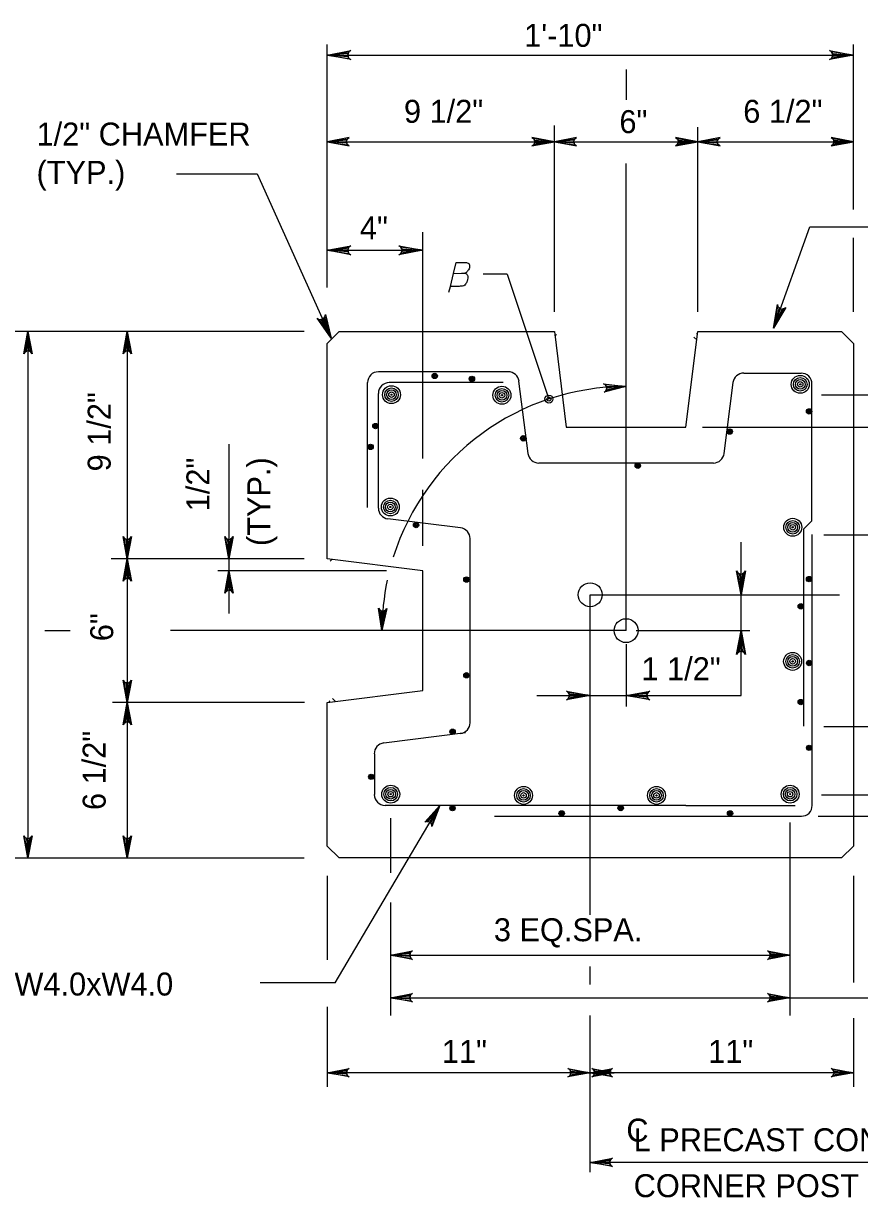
# Model space of a CAD drawing. Extents: x 3351 to 8430, y -3586 to 1457.
# Drawn here: x 5121.6 to 5233.4, y 162.9 to 319.9 of the extents above; entities that cross this region are included whole.
import ezdxf

# ---------------------------------------------------------------- set-up
doc = ezdxf.new("R2010")
doc.units = 0
doc.layers.add('1', color=7, linetype='Continuous')

msp = doc.modelspace()

# ---------------------------------------------------------------- linework, layer by layer
at = {"layer": '1'}
for p, q in [((5162.22, 284.6), (5162.22, 317.1)), ((5232.6, 295.01), (5232.6, 317.1)), ((5162.22, 315.67), (5232.6, 315.67)), ((5202.2, 313.73), (5202.2, 309.67)), ((5192.61, 281.36), (5192.61, 306.24)), ((5211.8, 281.36), (5211.8, 306.05)), ((5162.21, 304.09), (5192.61, 304.09)), ((5192.61, 304.09), (5211.8, 304.09)), ((5211.8, 304.09), (5232.6, 304.09)), ((5202.2, 238.72), (5202.2, 301.2)), ((5142.08, 299.79), (5152.85, 299.79)), ((5175.02, 261.75), (5175.02, 292)), ((5221.93, 279.14), (5226.77, 292.7)), ((5226.77, 292.7), (5234.76, 292.7)), ((5232.6, 281.36), (5232.6, 291.22)), ((5162.22, 289.57), (5175.02, 289.57)), ((5186.32, 286.38), (5183.09, 286.38)), ((5186.32, 286.38), (5191.88, 269.68)), ((5159.15, 278.72), (5120.24, 278.72)), ((5122.21, 278.72), (5122.21, 208.32)), ((5135.5, 278.72), (5135.5, 248.31)), ((5162.22, 277.12), (5163.82, 278.72)), ((5163.81, 278.72), (5192.61, 278.72)), ((5192.61, 278.72), (5194.21, 265.92)), ((5192.92, 278.33), (5192.68, 278.1)), ((5210.2, 265.92), (5211.8, 278.72)), ((5211.66, 277.58), (5211.26, 277.98)), ((5211.75, 278.3), (5211.6, 278.45)), ((5211.8, 278.72), (5231, 278.72)), ((5231, 278.72), (5232.6, 277.12)), ((5162.22, 248.31), (5162.22, 277.12)), ((5232.6, 277.12), (5232.6, 209.92)), ((5186.45, 273.33), (5169.08, 273.33)), ((5217.93, 273.15), (5225.6, 273.15)), ((5167.63, 255.18), (5167.63, 271.88)), ((5185.75, 271.88), (5170.53, 271.88)), ((5189.09, 262.4), (5187.88, 272.06)), ((5215.31, 262.4), (5216.5, 271.88)), ((5227.04, 253.41), (5227.04, 271.7)), ((5169.08, 255.11), (5169.08, 270.43)), ((5228.35, 270.27), (5236.82, 270.27)), ((5194.21, 265.92), (5210.2, 265.92)), ((5212.4, 265.92), (5245.08, 265.92)), ((5149.09, 263.63), (5149.09, 248.31)), ((5213.88, 261.13), (5190.52, 261.13)), ((5175.02, 250.07), (5175.02, 257.56)), ((5180.07, 252.46), (5170.35, 253.67)), ((5225.95, 252.31), (5227.04, 253.41)), ((5225.95, 225.96), (5225.95, 252.31)), ((5227.08, 215.36), (5227.08, 251.56)), ((5228.63, 251.51), (5244.51, 251.51)), ((5181.34, 226.41), (5181.34, 251.02)), ((5217.58, 230.05), (5217.58, 250.55)), ((5159.15, 248.31), (5133.35, 248.31)), ((5135.5, 248.31), (5135.5, 229.12)), ((5149.09, 248.31), (5149.09, 246.71)), ((5175.02, 246.71), (5162.22, 248.31)), ((5162.61, 248), (5162.84, 248.24)), ((5170.16, 246.71), (5147.6, 246.71)), ((5149.09, 246.71), (5149.09, 241.01)), ((5175.02, 230.72), (5175.02, 246.71)), ((5197.41, 243.52), (5230.75, 243.52)), ((5197.41, 200.73), (5197.41, 243.52)), ((5197.41, 243.52), (5197.41, 243.52)), ((5124.48, 238.72), (5127.87, 238.72)), ((5202.2, 238.72), (5141.28, 238.72)), ((5202.2, 238.72), (5202.2, 238.72)), ((5203.53, 238.72), (5218.77, 238.72)), ((5202.2, 236.92), (5202.2, 228.57)), ((5162.22, 229.12), (5175.02, 230.72)), ((5162.64, 229.17), (5162.49, 229.32)), ((5163.36, 229.26), (5162.96, 229.66)), ((5190.27, 230.05), (5217.58, 230.05)), ((5159.22, 229.12), (5133.54, 229.12)), ((5135.5, 229.12), (5135.5, 208.32)), ((5162.22, 209.92), (5162.22, 229.12)), ((5180.72, 225.05), (5169.8, 223.69)), ((5228.63, 225.92), (5244.81, 225.92)), ((5168.54, 222.26), (5168.54, 216.81)), ((5228.35, 216.77), (5241.27, 216.77)), ((5163.29, 191.65), (5177.28, 215.36)), ((5210.21, 215.36), (5169.98, 215.36)), ((5210.21, 215.36), (5224.83, 215.36)), ((5170.68, 213.66), (5170.68, 206.34)), ((5184.61, 213.91), (5225.64, 213.91)), ((5227.89, 213.91), (5245.08, 213.91)), ((5224.09, 213.06), (5224.09, 187.28)), ((5163.82, 208.32), (5162.22, 209.92)), ((5232.6, 209.92), (5231, 208.32)), ((5120.24, 208.32), (5159.15, 208.32)), ((5231, 208.32), (5163.82, 208.32)), ((5162.22, 205.94), (5162.22, 194.71)), ((5232.6, 205.94), (5232.6, 191.67)), ((5170.68, 202.36), (5170.68, 187.28)), ((5170.68, 195.33), (5224.09, 195.33)), ((5197.41, 191.4), (5197.41, 193.79)), ((5163.29, 191.65), (5153.25, 191.65)), ((5162.22, 188.43), (5162.22, 177.74)), ((5170.68, 189.64), (5224.09, 189.64)), ((5224.09, 189.64), (5237.91, 189.64)), ((5197.41, 166.32), (5197.41, 187.28)), ((5232.6, 186.91), (5232.6, 177.74)), ((5197.41, 179.6), (5162.21, 179.6)), ((5232.61, 179.6), (5197.41, 179.6)), ((5258.68, 167.61), (5197.41, 167.61))]:
    msp.add_line(p, q, dxfattribs=at)
for points in [[(5162.22, 315.67), (5165.4, 316.27), (5165.15, 316.1), (5165.03, 315.88), (5164.99, 315.67), (5165.03, 315.46), (5165.15, 315.24), (5165.4, 315.07), (5162.22, 315.67), (5165.15, 315.24), (5165.03, 315.46), (5162.22, 315.67), (5164.99, 315.67), (5165.03, 315.88), (5162.22, 315.67), (5165.15, 316.1)], [(5232.6, 315.67), (5229.42, 315.07), (5229.67, 315.24), (5229.79, 315.46), (5229.83, 315.67), (5229.79, 315.88), (5229.67, 316.1), (5229.42, 316.27), (5232.6, 315.67), (5229.67, 316.1), (5229.79, 315.88), (5232.6, 315.67), (5229.83, 315.67), (5229.79, 315.46), (5232.6, 315.67), (5229.67, 315.24)], [(5162.21, 304.09), (5165.19, 303.53), (5164.96, 303.69), (5164.84, 303.89), (5164.81, 304.09), (5164.84, 304.29), (5164.96, 304.49), (5165.19, 304.65), (5162.21, 304.09), (5164.96, 304.49), (5164.84, 304.29), (5162.21, 304.09), (5164.81, 304.09), (5164.84, 303.89), (5162.21, 304.09), (5164.96, 303.69)], [(5192.61, 304.09), (5189.62, 304.65), (5189.85, 304.49), (5189.97, 304.29), (5190.01, 304.09), (5189.97, 303.89), (5189.85, 303.69), (5189.62, 303.53), (5192.61, 304.09), (5189.85, 303.69), (5189.97, 303.89), (5192.61, 304.09), (5190.01, 304.09), (5189.97, 304.29), (5192.61, 304.09), (5189.85, 304.49)], [(5192.61, 304.09), (5195.59, 303.53), (5195.36, 303.69), (5195.24, 303.89), (5195.21, 304.09), (5195.24, 304.29), (5195.36, 304.49), (5195.59, 304.65), (5192.61, 304.09), (5195.36, 304.49), (5195.24, 304.29), (5192.61, 304.09), (5195.21, 304.09), (5195.24, 303.89), (5192.61, 304.09), (5195.36, 303.69)], [(5211.8, 304.09), (5208.82, 304.65), (5209.05, 304.49), (5209.17, 304.29), (5209.2, 304.09), (5209.17, 303.89), (5209.05, 303.69), (5208.82, 303.53), (5211.8, 304.09), (5209.05, 303.69), (5209.17, 303.89), (5211.8, 304.09), (5209.2, 304.09), (5209.17, 304.29), (5211.8, 304.09), (5209.05, 304.49)], [(5211.8, 304.09), (5214.79, 303.53), (5214.56, 303.69), (5214.44, 303.89), (5214.4, 304.09), (5214.44, 304.29), (5214.56, 304.49), (5214.79, 304.65), (5211.8, 304.09), (5214.56, 304.49), (5214.44, 304.29), (5211.8, 304.09), (5214.4, 304.09), (5214.44, 303.89), (5211.8, 304.09), (5214.56, 303.69)], [(5232.6, 304.09), (5229.62, 304.65), (5229.85, 304.49), (5229.97, 304.29), (5230, 304.09), (5229.97, 303.89), (5229.85, 303.69), (5229.62, 303.53), (5232.6, 304.09), (5229.85, 303.69), (5229.97, 303.89), (5232.6, 304.09), (5230, 304.09), (5229.97, 304.29), (5232.6, 304.09), (5229.85, 304.49)], [(5152.88, 299.79), (5162.75, 277.83)], [(5162.22, 289.57), (5165.4, 290.17), (5165.15, 290), (5165.03, 289.78), (5164.99, 289.57), (5165.03, 289.36), (5165.15, 289.14), (5165.4, 288.97), (5162.22, 289.57), (5165.15, 289.14), (5165.03, 289.36), (5162.22, 289.57), (5164.99, 289.57), (5165.03, 289.78), (5162.22, 289.57), (5165.15, 290)], [(5175.02, 289.57), (5171.83, 288.97), (5172.08, 289.14), (5172.21, 289.36), (5172.24, 289.57), (5172.21, 289.78), (5172.08, 290), (5171.83, 290.17), (5175.02, 289.57), (5172.08, 290), (5172.21, 289.78), (5175.02, 289.57), (5172.24, 289.57), (5172.21, 289.36), (5175.02, 289.57), (5172.08, 289.14)], [(5179.13, 286.48), (5179.48, 287.95), (5180.85, 287.95)], [(5179.93, 284.75), (5178.71, 284.75), (5179.13, 286.48), (5180.24, 286.5)], [(5178.52, 283.97), (5178.71, 284.75)], [(5221.93, 279.14), (5222.44, 282.34), (5222.51, 282.05), (5222.67, 281.86), (5222.86, 281.76), (5223.07, 281.72), (5223.32, 281.77), (5223.56, 281.94), (5221.93, 279.14), (5223.32, 281.77), (5223.07, 281.72), (5221.93, 279.14), (5222.86, 281.76), (5222.67, 281.86), (5221.93, 279.14), (5222.51, 282.05)], [(5162.75, 277.83), (5160.9, 280.48), (5161.16, 280.33), (5161.4, 280.3), (5161.61, 280.36), (5161.79, 280.48), (5161.93, 280.68), (5161.99, 280.97), (5162.75, 277.83), (5161.93, 280.68), (5161.79, 280.48), (5162.75, 277.83), (5161.61, 280.36), (5161.4, 280.3), (5162.75, 277.83), (5161.16, 280.33)], [(5122.21, 278.72), (5122.77, 275.74), (5122.61, 275.97), (5122.41, 276.09), (5122.21, 276.12), (5122.01, 276.09), (5121.81, 275.97), (5121.65, 275.74), (5122.21, 278.72), (5121.81, 275.97), (5122.01, 276.09), (5122.21, 278.72), (5122.21, 276.12), (5122.41, 276.09), (5122.21, 278.72), (5122.61, 275.97)], [(5135.5, 278.72), (5136.06, 275.74), (5135.9, 275.97), (5135.7, 276.09), (5135.5, 276.12), (5135.3, 276.09), (5135.1, 275.97), (5134.94, 275.74), (5135.5, 278.72), (5135.1, 275.97), (5135.3, 276.09), (5135.5, 278.72), (5135.5, 276.12), (5135.7, 276.09), (5135.5, 278.72), (5135.9, 275.97)], [(5202.2, 271.36), (5199.27, 270.6), (5199.48, 270.78), (5199.59, 270.99), (5199.61, 271.19), (5199.56, 271.38), (5199.43, 271.58), (5199.19, 271.72), (5202.2, 271.36), (5199.43, 271.58), (5199.56, 271.38), (5202.2, 271.36), (5199.61, 271.19), (5199.59, 270.99), (5202.2, 271.36), (5199.48, 270.78)], [(5135.5, 248.31), (5134.94, 251.3), (5135.1, 251.07), (5135.3, 250.95), (5135.5, 250.91), (5135.7, 250.95), (5135.9, 251.07), (5136.06, 251.3), (5135.5, 248.31), (5135.9, 251.07), (5135.7, 250.95), (5135.5, 248.31), (5135.5, 250.91), (5135.3, 250.95), (5135.5, 248.31), (5135.1, 251.07)], [(5149.09, 248.31), (5148.53, 251.3), (5148.69, 251.07), (5148.89, 250.95), (5149.09, 250.91), (5149.29, 250.95), (5149.49, 251.07), (5149.65, 251.3), (5149.09, 248.31), (5149.49, 251.07), (5149.29, 250.95), (5149.09, 248.31), (5149.09, 250.91), (5148.89, 250.95), (5149.09, 248.31), (5148.69, 251.07)], [(5135.5, 248.31), (5136.06, 245.33), (5135.9, 245.56), (5135.7, 245.68), (5135.5, 245.71), (5135.3, 245.68), (5135.1, 245.56), (5134.94, 245.33), (5135.5, 248.31), (5135.1, 245.56), (5135.3, 245.68), (5135.5, 248.31), (5135.5, 245.71), (5135.7, 245.68), (5135.5, 248.31), (5135.9, 245.56)], [(5149.09, 246.71), (5149.65, 243.73), (5149.49, 243.96), (5149.29, 244.08), (5149.09, 244.11), (5148.89, 244.08), (5148.69, 243.96), (5148.53, 243.73), (5149.09, 246.71), (5148.69, 243.96), (5148.89, 244.08), (5149.09, 246.71), (5149.09, 244.11), (5149.29, 244.08), (5149.09, 246.71), (5149.49, 243.96)], [(5217.58, 243.52), (5216.98, 246.7), (5217.15, 246.46), (5217.37, 246.33), (5217.58, 246.29), (5217.79, 246.33), (5218.01, 246.46), (5218.18, 246.7), (5217.58, 243.52), (5218.01, 246.46), (5217.79, 246.33), (5217.58, 243.52), (5217.58, 246.29), (5217.37, 246.33), (5217.58, 243.52), (5217.15, 246.46)], [(5169.56, 238.72), (5169.1, 241.71), (5169.26, 241.48), (5169.45, 241.35), (5169.65, 241.31), (5169.85, 241.34), (5170.05, 241.45), (5170.22, 241.68), (5169.56, 238.72), (5170.05, 241.45), (5169.85, 241.34), (5169.56, 238.72), (5169.65, 241.31), (5169.45, 241.35), (5169.56, 238.72), (5169.26, 241.48)], [(5217.58, 238.72), (5218.18, 235.54), (5218.01, 235.78), (5217.79, 235.91), (5217.58, 235.95), (5217.37, 235.91), (5217.15, 235.78), (5216.98, 235.54), (5217.58, 238.72), (5217.15, 235.78), (5217.37, 235.91), (5217.58, 238.72), (5217.58, 235.95), (5217.79, 235.91), (5217.58, 238.72), (5218.01, 235.78)], [(5135.5, 229.12), (5134.94, 232.1), (5135.1, 231.87), (5135.3, 231.75), (5135.5, 231.72), (5135.7, 231.75), (5135.9, 231.87), (5136.06, 232.1), (5135.5, 229.12), (5135.9, 231.87), (5135.7, 231.75), (5135.5, 229.12), (5135.5, 231.72), (5135.3, 231.75), (5135.5, 229.12), (5135.1, 231.87)], [(5197.41, 230.05), (5194.23, 229.45), (5194.47, 229.62), (5194.6, 229.83), (5194.64, 230.05), (5194.6, 230.26), (5194.47, 230.47), (5194.23, 230.64), (5197.41, 230.05), (5194.47, 230.47), (5194.6, 230.26), (5197.41, 230.05), (5194.64, 230.05), (5194.6, 229.83), (5197.41, 230.05), (5194.47, 229.62)], [(5202.2, 230.05), (5205.39, 230.64), (5205.14, 230.47), (5205.01, 230.26), (5204.98, 230.05), (5205.01, 229.83), (5205.14, 229.62), (5205.39, 229.45), (5202.2, 230.05), (5205.14, 229.62), (5205.01, 229.83), (5202.2, 230.05), (5204.98, 230.05), (5205.01, 230.26), (5202.2, 230.05), (5205.14, 230.47)], [(5135.5, 229.12), (5136.06, 226.13), (5135.9, 226.36), (5135.7, 226.48), (5135.5, 226.52), (5135.3, 226.48), (5135.1, 226.36), (5134.94, 226.13), (5135.5, 229.12), (5135.1, 226.36), (5135.3, 226.48), (5135.5, 229.12), (5135.5, 226.52), (5135.7, 226.48), (5135.5, 229.12), (5135.9, 226.36)], [(5177.28, 215.36), (5176.22, 212.52), (5176.21, 212.8), (5176.1, 213), (5175.94, 213.13), (5175.75, 213.21), (5175.52, 213.21), (5175.27, 213.09), (5177.28, 215.36), (5175.52, 213.21), (5175.75, 213.21), (5177.28, 215.36), (5175.94, 213.13), (5176.1, 213), (5177.28, 215.36), (5176.21, 212.8)], [(5122.21, 208.32), (5121.65, 211.3), (5121.81, 211.07), (5122.01, 210.95), (5122.21, 210.92), (5122.41, 210.95), (5122.61, 211.07), (5122.77, 211.3), (5122.21, 208.32), (5122.61, 211.07), (5122.41, 210.95), (5122.21, 208.32), (5122.21, 210.92), (5122.01, 210.95), (5122.21, 208.32), (5121.81, 211.07)], [(5135.5, 208.32), (5134.94, 211.3), (5135.1, 211.07), (5135.3, 210.95), (5135.5, 210.92), (5135.7, 210.95), (5135.9, 211.07), (5136.06, 211.3), (5135.5, 208.32), (5135.9, 211.07), (5135.7, 210.95), (5135.5, 208.32), (5135.5, 210.92), (5135.3, 210.95), (5135.5, 208.32), (5135.1, 211.07)], [(5170.68, 195.33), (5173.66, 195.89), (5173.43, 195.73), (5173.31, 195.53), (5173.28, 195.33), (5173.31, 195.13), (5173.43, 194.93), (5173.66, 194.77), (5170.68, 195.33), (5173.43, 194.93), (5173.31, 195.13), (5170.68, 195.33), (5173.28, 195.33), (5173.31, 195.53), (5170.68, 195.33), (5173.43, 195.73)], [(5224.09, 195.33), (5221.1, 194.77), (5221.33, 194.93), (5221.45, 195.13), (5221.49, 195.33), (5221.45, 195.53), (5221.33, 195.73), (5221.1, 195.89), (5224.09, 195.33), (5221.33, 195.73), (5221.45, 195.53), (5224.09, 195.33), (5221.49, 195.33), (5221.45, 195.13), (5224.09, 195.33), (5221.33, 194.93)], [(5170.68, 189.64), (5173.66, 190.2), (5173.43, 190.04), (5173.31, 189.84), (5173.28, 189.64), (5173.31, 189.44), (5173.43, 189.24), (5173.66, 189.08), (5170.68, 189.64), (5173.43, 189.24), (5173.31, 189.44), (5170.68, 189.64), (5173.28, 189.64), (5173.31, 189.84), (5170.68, 189.64), (5173.43, 190.04)], [(5224.09, 189.64), (5221.1, 189.08), (5221.33, 189.24), (5221.45, 189.44), (5221.49, 189.64), (5221.45, 189.84), (5221.33, 190.04), (5221.1, 190.2), (5224.09, 189.64), (5221.33, 190.04), (5221.45, 189.84), (5224.09, 189.64), (5221.49, 189.64), (5221.45, 189.44), (5224.09, 189.64), (5221.33, 189.24)], [(5162.21, 179.6), (5165.19, 180.16), (5164.97, 180), (5164.85, 179.8), (5164.81, 179.6), (5164.85, 179.4), (5164.97, 179.2), (5165.19, 179.04), (5162.21, 179.6), (5164.97, 179.2), (5164.85, 179.4), (5162.21, 179.6), (5164.81, 179.6), (5164.85, 179.8), (5162.21, 179.6), (5164.97, 180)], [(5197.41, 179.6), (5194.43, 179.04), (5194.66, 179.2), (5194.77, 179.4), (5194.81, 179.6), (5194.77, 179.8), (5194.66, 180), (5194.43, 180.16), (5197.41, 179.6), (5194.66, 180), (5194.77, 179.8), (5197.41, 179.6), (5194.81, 179.6), (5194.77, 179.4), (5197.41, 179.6), (5194.66, 179.2)], [(5197.41, 179.6), (5200.39, 180.16), (5200.16, 180), (5200.04, 179.8), (5200.01, 179.6), (5200.04, 179.4), (5200.16, 179.2), (5200.39, 179.04), (5197.41, 179.6), (5200.16, 179.2), (5200.04, 179.4), (5197.41, 179.6), (5200.01, 179.6), (5200.04, 179.8), (5197.41, 179.6), (5200.16, 180)], [(5200.61, 179.6), (5197.63, 179.04), (5197.86, 179.2), (5197.98, 179.4), (5198.01, 179.6), (5197.98, 179.8), (5197.86, 180), (5197.63, 180.16), (5200.61, 179.6), (5197.86, 180), (5197.98, 179.8), (5200.61, 179.6), (5198.01, 179.6), (5197.98, 179.4), (5200.61, 179.6), (5197.86, 179.2)], [(5232.61, 179.6), (5229.62, 179.04), (5229.85, 179.2), (5229.97, 179.4), (5230.01, 179.6), (5229.97, 179.8), (5229.85, 180), (5229.62, 180.16), (5232.61, 179.6), (5229.85, 180), (5229.97, 179.8), (5232.61, 179.6), (5230.01, 179.6), (5229.97, 179.4), (5232.61, 179.6), (5229.85, 179.2)], [(5197.41, 167.61), (5200.39, 168.17), (5200.16, 168.01), (5200.04, 167.81), (5200.01, 167.61), (5200.04, 167.41), (5200.16, 167.21), (5200.39, 167.05), (5197.41, 167.61), (5200.16, 167.21), (5200.04, 167.41), (5197.41, 167.61), (5200.01, 167.61), (5200.04, 167.81), (5197.41, 167.61), (5200.16, 168.01)]]:
    msp.add_lwpolyline(points, dxfattribs=at)
for centre, radius in [((5176.61, 272.77), 0.36), ((5176.61, 272.77), 0.272), ((5176.61, 272.77), 0.195), ((5176.61, 272.77), 0.11), ((5181.58, 272.38), 0.36), ((5181.58, 272.38), 0.272), ((5181.58, 272.38), 0.195), ((5181.58, 272.38), 0.11), ((5225.49, 271.65), 1.2), ((5225.49, 271.65), 0.906), ((5225.49, 271.65), 0.648), ((5225.49, 271.65), 0.367), ((5225.49, 271.65), 0.0862), ((5170.83, 270.27), 1.2), ((5170.83, 270.27), 0.906), ((5170.83, 270.27), 0.648), ((5170.83, 270.27), 0.367), ((5170.83, 270.27), 0.0862), ((5185.6, 270.19), 1.2), ((5185.6, 270.19), 0.906), ((5185.6, 270.19), 0.648), ((5185.6, 270.19), 0.367), ((5185.6, 270.19), 0.0862), ((5191.88, 269.68), 0.533), ((5191.88, 269.68), 0.267), ((5226.67, 268.03), 0.36), ((5226.67, 268.03), 0.272), ((5226.67, 268.03), 0.195), ((5226.67, 268.03), 0.11), ((5168.68, 266.07), 0.36), ((5168.68, 266.07), 0.272), ((5168.68, 266.07), 0.195), ((5168.68, 266.07), 0.11), ((5216.06, 265.34), 0.36), ((5216.06, 265.34), 0.272), ((5216.06, 265.34), 0.195), ((5216.06, 265.34), 0.11), ((5188.46, 264.43), 0.36), ((5188.46, 264.43), 0.272), ((5188.46, 264.43), 0.195), ((5188.46, 264.43), 0.11), ((5168.04, 263.29), 0.36), ((5168.04, 263.29), 0.272), ((5168.04, 263.29), 0.195), ((5168.04, 263.29), 0.11), ((5203.77, 260.77), 0.36), ((5203.77, 260.77), 0.272), ((5203.77, 260.77), 0.195), ((5203.77, 260.77), 0.11), ((5170.68, 255.25), 1.2), ((5170.68, 255.25), 0.906), ((5170.68, 255.25), 0.648), ((5170.68, 255.25), 0.367), ((5170.68, 255.25), 0.0862), ((5174.12, 252.84), 0.36), ((5174.12, 252.84), 0.272), ((5174.12, 252.84), 0.195), ((5174.12, 252.84), 0.11), ((5224.49, 252.54), 1.2), ((5224.49, 252.54), 0.906), ((5224.49, 252.54), 0.648), ((5224.49, 252.54), 0.367), ((5224.49, 252.54), 0.0862), ((5180.85, 245.55), 0.36), ((5180.85, 245.55), 0.272), ((5180.85, 245.55), 0.195), ((5180.85, 245.55), 0.11), ((5197.41, 243.52), 1.6), ((5226.68, 245.61), 0.36), ((5226.68, 245.61), 0.272), ((5226.68, 245.61), 0.195), ((5226.68, 245.61), 0.11), ((5225.56, 241.97), 0.36), ((5225.56, 241.97), 0.272), ((5225.56, 241.97), 0.195), ((5225.56, 241.97), 0.11), ((5202.2, 238.72), 1.6), ((5224.47, 234.61), 1.2), ((5224.47, 234.61), 0.906), ((5224.47, 234.61), 0.648), ((5224.47, 234.61), 0.367), ((5224.47, 234.61), 0.0862), ((5226.69, 234.39), 0.36), ((5226.69, 234.39), 0.272), ((5226.69, 234.39), 0.195), ((5226.69, 234.39), 0.11), ((5180.85, 232.75), 0.36), ((5180.85, 232.75), 0.272), ((5180.85, 232.75), 0.195), ((5180.85, 232.75), 0.11), ((5225.56, 229.17), 0.36), ((5225.56, 229.17), 0.272), ((5225.56, 229.17), 0.195), ((5225.56, 229.17), 0.11), ((5179, 225.2), 0.36), ((5179, 225.2), 0.272), ((5179, 225.2), 0.195), ((5179, 225.2), 0.11), ((5226.69, 223.05), 0.36), ((5226.69, 223.05), 0.272), ((5226.69, 223.05), 0.195), ((5226.69, 223.05), 0.11), ((5168.13, 219.17), 0.36), ((5168.13, 219.17), 0.272), ((5168.13, 219.17), 0.195), ((5168.13, 219.17), 0.11), ((5170.73, 216.85), 1.2), ((5170.73, 216.85), 0.906), ((5170.73, 216.85), 0.648), ((5170.73, 216.85), 0.367), ((5170.73, 216.85), 0.0862), ((5188.49, 216.69), 1.2), ((5188.49, 216.69), 0.906), ((5188.49, 216.69), 0.648), ((5188.49, 216.69), 0.367), ((5188.49, 216.69), 0.0862), ((5206.27, 216.69), 1.2), ((5206.27, 216.69), 0.906), ((5206.27, 216.69), 0.648), ((5206.27, 216.69), 0.367), ((5206.27, 216.69), 0.0862), ((5224.14, 216.85), 1.2), ((5224.14, 216.85), 0.906), ((5224.14, 216.85), 0.648), ((5224.14, 216.85), 0.367), ((5224.14, 216.85), 0.0862), ((5178.99, 214.99), 0.36), ((5178.99, 214.99), 0.272), ((5178.99, 214.99), 0.195), ((5178.99, 214.99), 0.11), ((5201.48, 215), 0.36), ((5201.48, 215), 0.272), ((5201.48, 215), 0.195), ((5201.48, 215), 0.11), ((5193.59, 214.28), 0.36), ((5193.59, 214.28), 0.272), ((5193.59, 214.28), 0.195), ((5193.59, 214.28), 0.11), ((5216.11, 214.28), 0.36), ((5216.11, 214.28), 0.272), ((5216.11, 214.28), 0.195), ((5216.11, 214.28), 0.11)]:
    msp.add_circle(centre, radius, dxfattribs=at)
for centre, radius, start, end in [((5169.08, 271.88), 1.45, 90, 180), ((5186.45, 271.88), 1.45, 7.1086, 90), ((5217.93, 271.7), 1.45, 90, 172.8914), ((5225.6, 271.7), 1.45, 0, 90), ((5170.53, 270.43), 1.45, 90, 180), ((5202.2, 238.72), 32.64, 90, 162.5035), ((5190.52, 262.58), 1.45, 187.1086, 270), ((5213.88, 262.58), 1.45, 270, 352.8914), ((5170.53, 255.11), 1.45, 180, 262.8734), ((5179.89, 251.02), 1.45, 360, 82.8733), ((5202.2, 238.72), 32.64, 168.1031, 180), ((5179.89, 226.41), 1.45, 277.1086, 0), ((5169.98, 222.26), 1.45, 97.1874, 180), ((5169.98, 216.81), 1.45, 180, 270), ((5225.64, 215.36), 1.45, 270, 360)]:
    msp.add_arc(centre, radius, start, end, dxfattribs=at)
msp.add_spline([(5180.85, 287.95), (5181.08, 287.87), (5181.23, 287.7), (5181.26, 287.25), (5181.14, 286.98), (5180.98, 286.77), (5180.64, 286.5), (5180.24, 286.5), (5180.64, 286.5), (5180.98, 286.26), (5181.03, 285.86), (5180.95, 285.45), (5180.72, 285.04), (5180.51, 284.84), (5180.17, 284.78), (5179.9, 284.75)], degree=3, dxfattribs=at)

# ---------------------------------------------------------------- texts
for s, height, p in [('1\'-10"', 3.072, (5188.58, 316.78)), ('9 1/2"', 3.072, (5172.5, 306.62)), ('6 1/2"', 3.072, (5217.87, 306.62)), ('6"', 3.072, (5201.31, 305.24)), ('1/2" CHAMFER', 3.0721, (5123.37, 303.58)), ('(TYP.)', 3.072, (5123.37, 298.46)), ('4"', 3.072, (5166.61, 291.03)), ('1 1/2"', 3.072, (5204.26, 232.08)), ('3 EQ.SPA.', 3.072, (5184.52, 197.19)), ('4x4-W4.0xW4.0', 3.0721, (5112.42, 189.93)), ('11"', 3.072, (5177.57, 180.92)), ('11"', 3.072, (5213.18, 180.92)), ('C', 3.07, (5202.24, 170.4)), ('L PRECAST CONCRETE', 3.0721, (5203.22, 169.11)), ('CORNER POST', 3.0721, (5203.22, 162.97))]:
    msp.add_text(s, height=height, dxfattribs=at).set_placement(p)
for s, p in [('9 1/2"', (5133.28, 260.01)), ('1/2"', (5146.48, 254.68)), ('(TYP.)', (5154.63, 250.03)), ('6"', (5133.62, 237.31)), ('6 1/2"', (5132.61, 214.73))]:
    msp.add_text(s, height=3.072, rotation=90, dxfattribs=at).set_placement(p)

doc.saveas('drawing.dxf')
